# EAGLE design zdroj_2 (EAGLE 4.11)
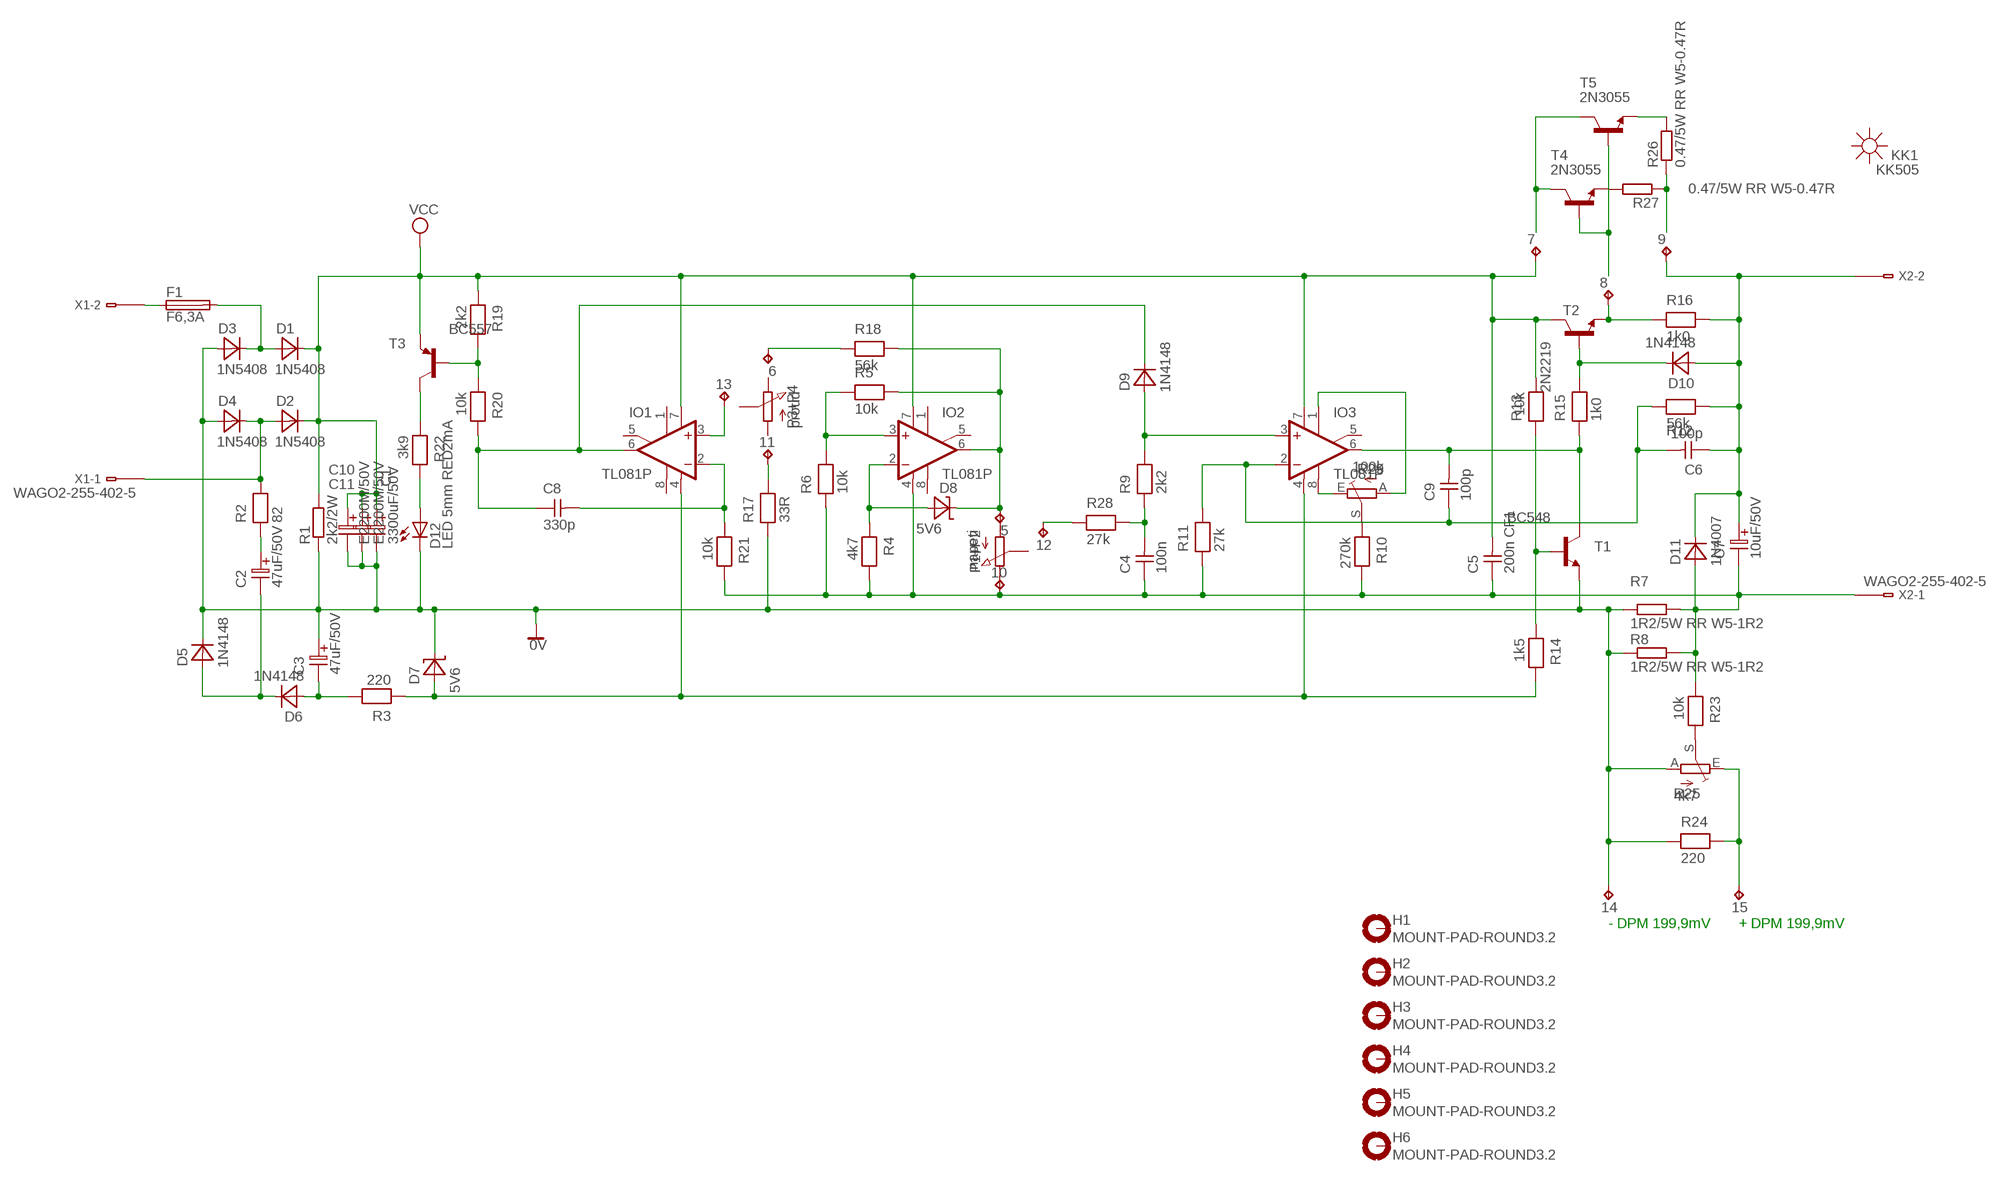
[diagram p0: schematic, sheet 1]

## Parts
5  TPPAD1-13Y  [P1-13Y]
6  TPPAD1-13Y  [P1-13Y]
7  TPPAD1-13Y  [P1-13Y]
8  TPPAD1-13Y  [P1-13Y]
9  TPPAD1-13Y  [P1-13Y]
10  TPPAD1-13Y  [P1-13Y]
11  TPPAD1-13Y  [P1-13Y]
12  TPPAD1-13Y  [P1-13Y]
13  TPPAD1-13Y  [P1-13Y]
14  TPPAD1-13Y  [P1-13Y]
15  TPPAD1-13Y  [P1-13Y]
C1  3300uF/50V  ELC-45L  [E-45L]
C2  47uF/50V  ELC-5  [ES-5]
C3  47uF/50V  ELC-5  [ES-5]
C4  100n  CAPNP-5  [C-5]
C5  200n CF1  CAPNP-5  [C-5]
C6  100p  CAPNP-5  [C-5]
C7  10uF/50V  ELC-2,5L  [ES-2,5L]
C8  330p  CAPNP-5  [C-5]
C9  100p  CAPNP-5  [C-5]
C10  E2200M/50V  ELC-7,5  [ES-7,5]
C11  E2200M/50V  ELC-7,5  [ES-7,5]
D1  1N5408  DIODE-12,5  [D-12,5]
D2  1N5408  DIODE-12,5  [D-12,5]
D3  1N5408  DIODE-12,5  [D-12,5]
D4  1N5408  DIODE-12,5  [D-12,5]
D5  1N4148  DIODE-7,5  [D-7,5]
D6  1N4148  DIODE-7,5  [D-7,5]
D7  5V6  ZDIO-7,5  [D-7,5]
D8  5V6  ZDIO-7,5  [D-7,5]
D9  1N4148  DIODE-7,5  [D-7,5]
D10  1N4148  DIODE-7,5  [D-7,5]
D11  1N4007  DIODE-7,5  [D-7,5]
D12  LED 5mm RED2mA  LED3MM  [LED3MM]
F1  F6,3A  SH22,5A  [SH22,5A]
H1  MOUNT-PAD-ROUND3.2  [3,2-PAD]
H2  MOUNT-PAD-ROUND3.2  [3,2-PAD]
H3  MOUNT-PAD-ROUND3.2  [3,2-PAD]
H4  MOUNT-PAD-ROUND3.2  [3,2-PAD]
H5  MOUNT-PAD-ROUND3.2  [3,2-PAD]
H6  MOUNT-PAD-ROUND3.2  [3,2-PAD]
IO1  TL081P  [DIL08]
IO2  TL081P  [DIL08]
IO3  TL081P  [DIL08]
KK1  KK505  [KK505]
P1+P2  napeti  PC25  [PC25]
P3+P4  proud  PC25  [PC25]
R1  2k2/2W  R-EU_0414/15  [0414/15]
R2  82  RESEU-7,5  [R-7,5]
R3  220  RESEU-7,5  [R-7,5]
R4  4k7  RESEU-7,5  [R-7,5]
R5  10k  RESEU-7,5  [R-7,5]
R6  10k  RESEU-7,5  [R-7,5]
R7  1R2/5W RR W5-1R2  R-EU_0922/22  [0922/22]
R8  1R2/5W RR W5-1R2  R-EU_0922/22  [0922/22]
R9  2k2  RESEU-7,5  [R-7,5]
R10  270k  RESEU-7,5  [R-7,5]
R11  27k  RESEU-7,5  [R-7,5]
R12  56k  RESEU-7,5  [R-7,5]
R13  10k  RESEU-7,5  [R-7,5]
R14  1k5  RESEU-7,5  [R-7,5]
R15  1k0  RESEU-7,5  [R-7,5]
R16  1k0  RESEU-7,5  [R-7,5]
R17  33R  RESEU-7,5  [R-7,5]
R18  56k  RESEU-7,5  [R-7,5]
R19  2k2  RESEU-7,5  [R-7,5]
R20  10k  RESEU-7,5  [R-7,5]
R21  10k  RESEU-7,5  [R-7,5]
R22  3k9  RESEU-7,5  [R-7,5]
R23  10k  RESEU-7,5  [R-7,5]
R24  220  RESEU-7,5  [R-7,5]
R25  4k7  TRIM_EU-CA6V  [CA6V]
R26  0.47/5W RR W5-0.47R  R-EU_0922/22  [0922/22]
R27  0.47/5W RR W5-0.47R  R-EU_0922/22  [0922/22]
R28  27k  RESEU-7,5  [R-7,5]
R29  100k  TRIM_EU-CA6V  [CA6V]
T1  BC548  [TO92-EBC]
T2  2N2219  [TO5]
T3  BC557  [TO92-EBC]
T4  2N3055  2N2219  [TO5]
T5  2N3055  2N2219  [TO5]
X1  WAGO2-255-402-5  [255-402-5]
X2  WAGO2-255-402-5  [255-402-5]

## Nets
0V: 14.1(TP) C1.2 C3.1 C10.2 C11.2 D3.1(A) D4.1(A) D5.2(K) D7.2(K) D12.K(C) R1.1 R7.1 R8.1 R17.1 R24.1 R25.A T1.E
N$1: D2.1(A) D4.2(K) R2.2 X1.B1(-1:B1)
N$2: D1.1(A) D3.2(K) F1.2
N$4: R23.2 R25.S
N$5: F1.1 X1.B2(-2:B1)
N$6: C3.2 D6.1(A) R3.2
N$7: D7.1(A) IO1.4(V-) IO3.4(V-) R3.1 R14.2
N$8: C2.2 D5.1(A) D6.2(K)
N$9: D12.A R22.2
N$10: C2.1 R2.1
N$12: R22.1 T3.C
N$13: R19.2 R20.1 T3.B
N$14: C8.1 D9.2(K) IO1.6(OUT) R20.2
N$15: C8.2 IO1.2(-IN) R21.1
N$16: 8.1(TP) R16.1 T2.1(E)
N$17: 13.1(TP) IO1.3(+IN)
N$18: 6.1(TP) R18.1
N$19: 5.1(TP) D8.2(K) IO2.6(OUT) R5.2 R18.2
N$20: 11.1(TP) R17.2
N$21: D8.1(A) IO2.2(-IN) R4.1
N$22: IO2.3(+IN) R5.1 R6.2
N$23: 12.1(TP) R28.1
N$24: C4.2 R9.1 R28.2
N$25: D9.1(A) IO3.3(+IN) R9.2
N$26: C6.2 C9.1 IO3.2(-IN) R11.2 R12.1
N$27: IO3.1(ON1) R29.A
N$28: IO3.8(OPT) R29.E
N$29: R10.1 R29.S
N$30: C9.2 IO3.6(OUT) R15.1 T1.C
N$31: R13.2 R14.1 T1.B
N$32: D10.2(K) R15.2 T2.2(B)
N$33: 15.1(TP) R24.2 R25.E
N$34: T4.3(C) T5.3(C)
N$35: 9.1(TP) C6.1 C7.1 D10.1(A) D11.2(K) R12.2 R16.2 X2.B2(-2:B1)
N$43: 10.1(TP) C4.1 C5.1 C7.2 D11.1(A) IO2.4(V-) R4.2 R6.1 R7.2 R8.2 R10.2 R11.1 R21.2 R23.1 X2.B1(-1:B1)
N$44: R27.2 T4.1(E)
N$45: R26.2 T5.1(E)
N$46: R26.1 R27.1
N$47: T4.2(B) T5.2(B)
VCC: 7.1(TP) C1.1 C5.2 C10.1 C11.1 D1.2(K) D2.2(K) IO1.7(V+) IO2.7(V+) IO3.7(V+) R1.2 R13.1 R19.1 T2.3(C) T3.E
Unconnected: H1.B3,2(MOUNT) H2.B3,2(MOUNT) H3.B3,2(MOUNT) H4.B3,2(MOUNT) H5.B3,2(MOUNT) H6.B3,2(MOUNT) IO1.1(ON1) IO1.5(ON2) IO1.8(OPT) IO2.1(ON1) IO2.5(ON2) IO2.8(OPT) IO3.5(ON2) P1+P2.A P1+P2.E P1+P2.S P3+P4.A P3+P4.E P3+P4.S X1.A1(-1:A1) X1.A2(-2:A1) X2.A1(-1:A1) X2.A2(-2:A1)

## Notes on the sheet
- - DPM 199,9mV | + DPM 199,9mV

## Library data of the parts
5-15 = testpad:TP
C1 = discrete:ELC-45L
C2 C3 = discrete:ELC-5
C4-C6 C8 C9 = discrete:CAPNP-5
C7 = discrete:ELC-2,5L
C10 C11 = discrete:ELC-7,5
D1-D4 = discrete:DIODE-12,5
D5 D6 D9-D11 = discrete:DIODE-7,5
D7 D8 = discrete:ZDIO-7,5
D12 = led:LED: LED
F1 = fuse:SH22,5A: FUSE HOLDER
H1-H6 = holes:MOUNT-PAD-ROUND: MOUNTING PAD, round
IO1-IO3 = linear:TL081: OP AMP
KK1 = heatsink:KK505: HEATSINK
P1+P2 P3+P4 = pot-vitrohm:PC25: VITROHM POTENTIOMETER
R1 R7 R8 R26 R27 = rcl:R-EU_: RESISTOR, European symbol
R2-R6 R9-R24 R28 = discrete:RESEU-7,5
R25 R29 = pot:TRIM_EU-: POTENTIOMETER
T1 = transistor-npn:BC548*: NPN Transistor
T2 T4 T5 = transistor-npn:2N2219: NPN Transistor
T3 = transistor-pnp:BC557*: PNP Transistror
X1 X2 = con-wago:WAGO2-: WAGO Cage Clamp

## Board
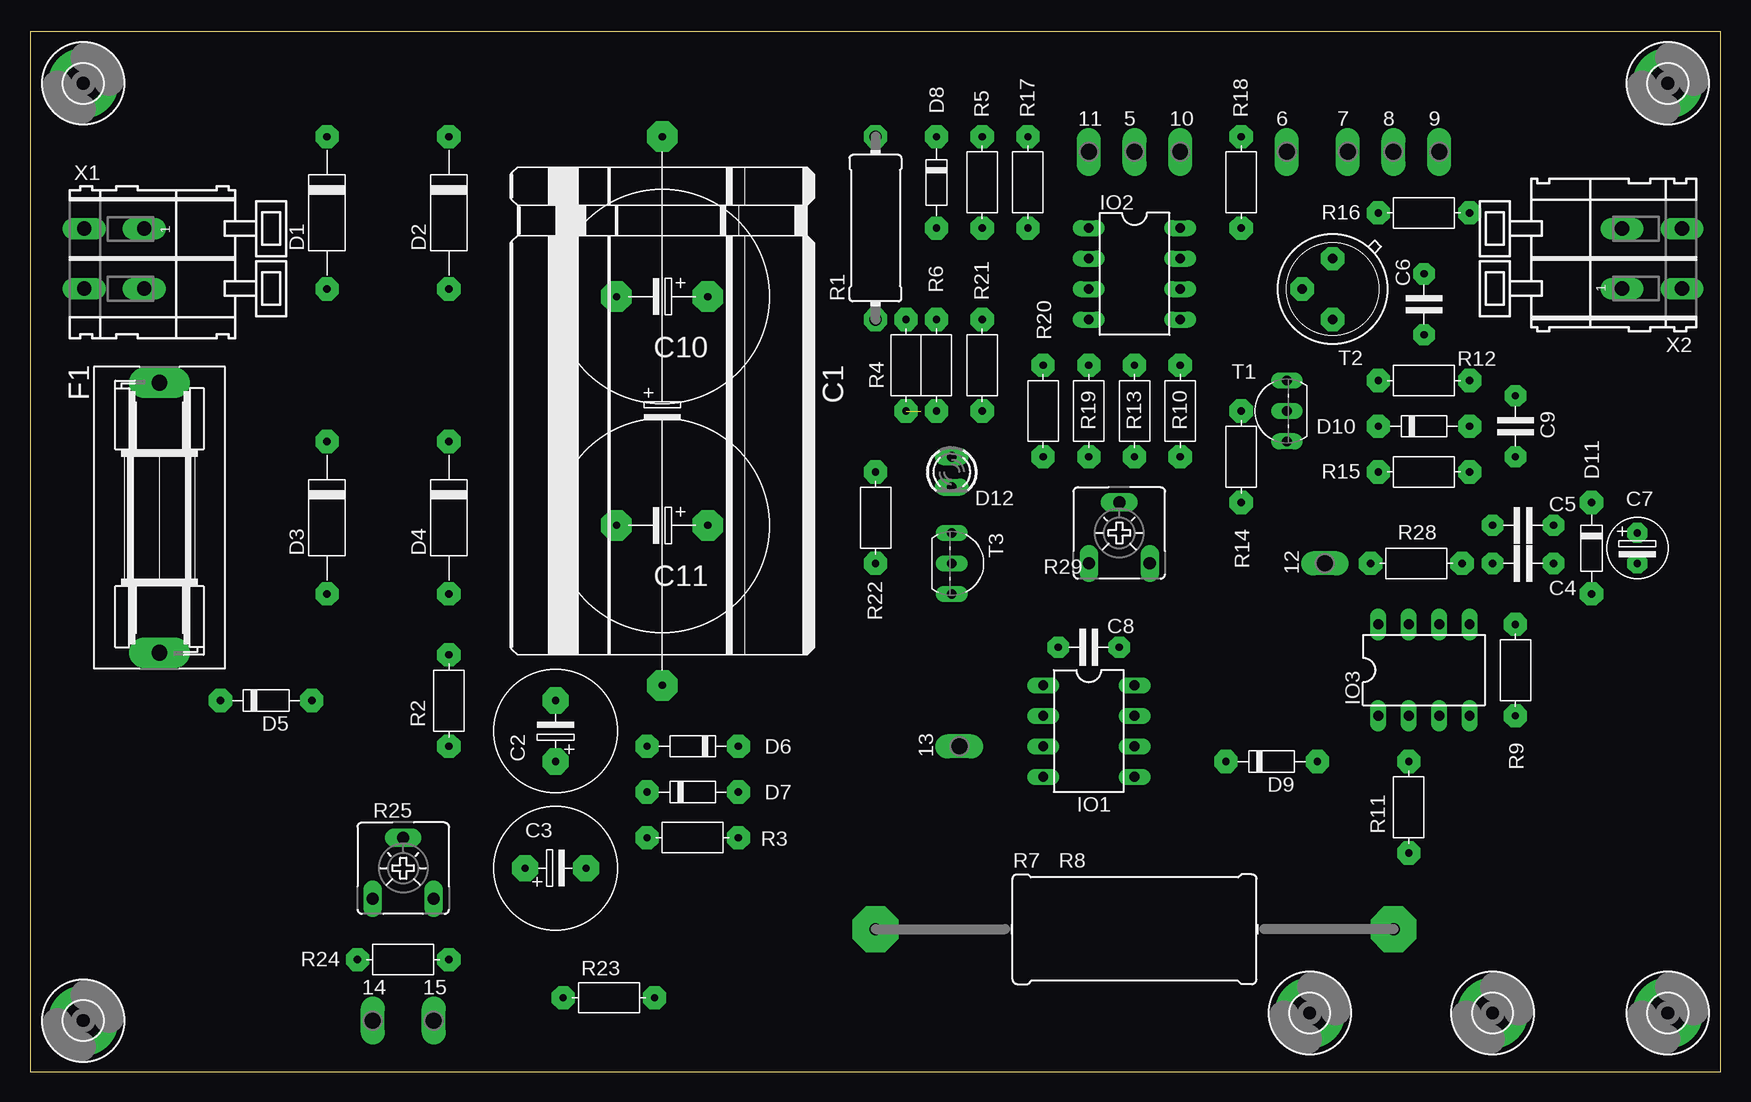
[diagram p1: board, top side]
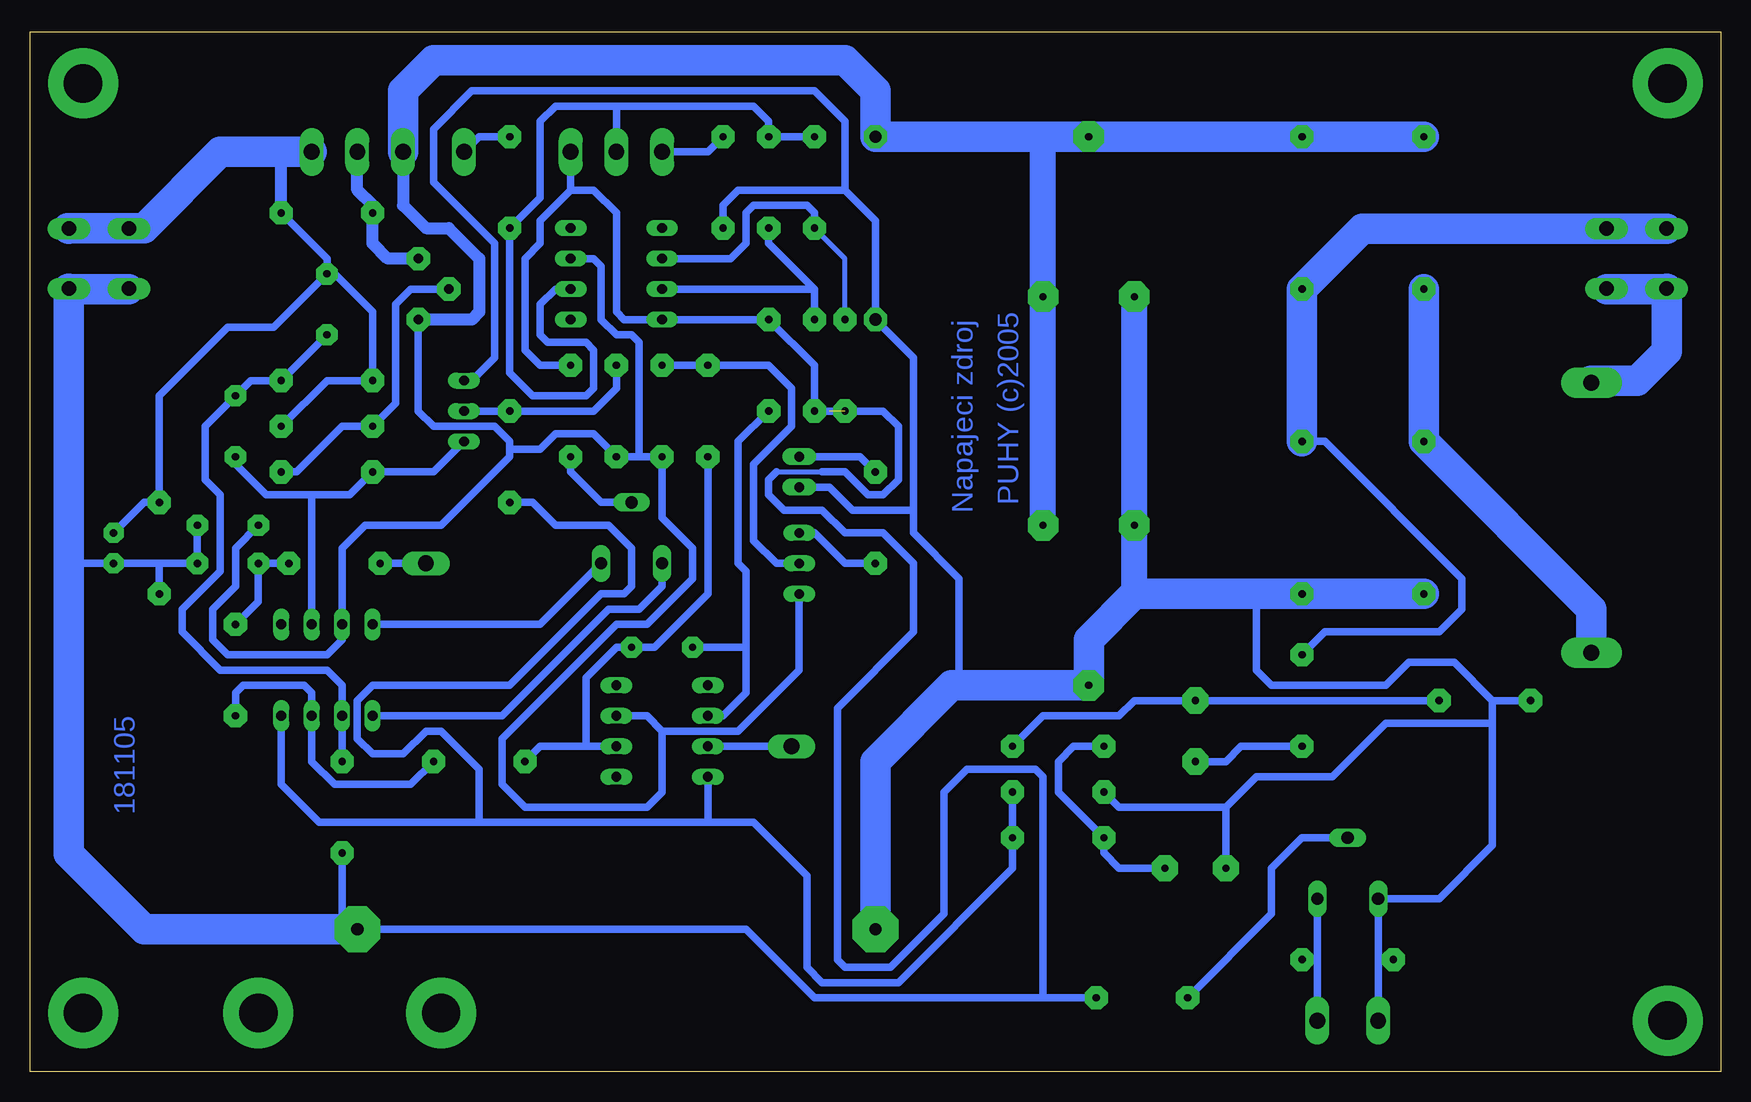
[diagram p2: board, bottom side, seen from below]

Size 140.95 x 86.67 mm. Coordinates in mm from the lower left corner, seen from the top.
Outline: 0,0 140.95,0 140.95,86.67 0,86.67 0,0
Copper layers (1*16): Top 0.035mm / dielectric 1.5mm / Bottom 0.035mm
Design rules "default": minimum track width 10mil, minimum drill 24mil, track to track 8mil, track to pad 8mil, pad to pad 8mil, via to via 8mil, smd to smd 8mil, copper to edge 40mil, drill to drill 8mil, minimum pad ring 10mil, minimum via ring 8mil, stop-mask expansion 4mil, vias tented up to drill 0mil, thermal gap 10mil

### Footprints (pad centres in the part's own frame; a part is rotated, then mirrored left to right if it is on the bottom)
P1-13Y = drill 1.321 pad 1.905 long: 1 0,0
E-45L = drill 0.61 pad 2.54 octagon: 1 0,0; 2 45.72,0
ES-5 = drill 0.61 pad 2.184 octagon: 1 -2.54,0; 2 2.54,0
C-5 = drill 0.61 pad 1.778 octagon: 1 -2.54,0; 2 2.54,0
ES-2,5L = drill 0.61 pad 1.676 octagon: 1 0,0; 2 2.54,0
ES-7,5 = drill 0.61 pad 2.54 octagon: 1 -3.81,0; 2 3.81,0
D-12,5 = drill 0.61 pad 1.93 octagon: 1 -6.35,0; 2 6.35,0
D-7,5 = drill 0.61 pad 1.93 octagon: 1 -3.81,0; 2 3.81,0
LED3MM = drill 0.813 pad 1.422 long: A -1.27,0; K 1.27,0
SH22,5A = drill 1.321 pad 2.54 long: 1 -11.252,0; 2 11.252,0
3,2-PAD = drill 3.2 pad 5.842 round: B3,2 0,0
DIL08 = drill 0.813 long: 1 -3.81,-3.81; 2 -1.27,-3.81; 3 1.27,-3.81; 4 3.81,-3.81; 5 3.81,3.81; 6 1.27,3.81; 7 -1.27,3.81; 8 -3.81,3.81
PC25 = smd 2.2 x 0.8: 4 0,1.65 | smd 0.9 x 1.4: A -1.35,-1.9; E 1.35,-1.9; S 0,-1.9
0414/15 = drill 1.016 pad 1.93 octagon: 1 -7.62,0; 2 7.62,0
R-7,5 = drill 0.61 pad 1.93 octagon: 1 -3.81,0; 2 3.81,0
0922/22 = drill 1.016 pad 3.81 octagon: 1 -21.59,0; 2 21.59,0
CA6V = drill 1.016 long: A -2.54,-2.54; E 2.54,-2.54; S 0,2.54
TO92-EBC = drill 0.813 long: B 0,-1.27; C -2.54,-1.27; E 2.54,-1.27
TO5 = drill 0.813 pad 1.93 octagon: 1 0,-2.54; 2 2.54,0; 3 0,2.54
255-402-5 = drill 1.2 long: A1 -2.5,0; A2 2.5,0; B1 -2.5,-5; B2 2.5,-5

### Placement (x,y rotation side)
5  92.07,76.67 0 top
6  104.77,76.67 0 top
7  109.85,76.67 0 top
8  113.66,76.67 0 top
9  117.47,76.67 0 top
10  95.88,76.67 0 top
11  88.26,76.67 0 top
12  107.94,42.38 90 top
13  77.47,27.14 90 top
14  28.57,4.28 0 top
15  33.65,4.28 0 top
C1  52.7,77.94 270 top
C2  43.81,28.41 90 top
C3  43.81,16.98 0 top
C4  124.46,42.38 180 top
C5  124.46,45.56 180 top
C6  116.2,63.97 270 top
C7  133.98,44.92 270 top
C8  88.26,35.39 180 top
C9  123.82,53.81 270 top
C10  52.7,64.61 180 top
C11  52.7,45.56 180 top
D1  24.76,71.59 90 top
D2  34.92,71.59 90 top
D3  24.76,46.19 90 top
D4  34.92,46.19 90 top
D5  19.68,30.95 180 top
D6  55.24,27.14 0 top
D7  55.24,23.33 180 top
D8  75.56,74.13 90 top
D9  103.5,25.87 180 top
D10  116.2,53.81 180 top
D11  130.17,43.65 90 top
D12  76.83,50 270 top
F1  10.79,46.19 270 top
H1  4.44,82.39 0 top
H2  4.44,4.28 0 top
H3  121.91,4.91 0 top
H4  136.52,4.91 0 top
H5  106.68,4.91 0 top
H6  136.52,82.39 0 top
IO1  88.26,28.41 270 top
IO2  92.07,66.51 270 top
IO3  116.2,33.49 0 top
KK1  not placed on the board
P1+P2  not placed on the board
P3+P4  not placed on the board
R1  70.48,70.32 90 top
R2  34.92,30.95 90 top
R3  55.24,19.52 180 top
R4  73.02,58.89 270 top
R5  79.37,74.13 90 top
R6  75.56,58.89 90 top
R7  92.07,11.9 0 top
R8  92.07,11.9 0 top
R9  123.82,33.49 270 top
R10  95.88,55.08 90 top
R11  114.93,22.06 90 top
R12  116.2,57.62 180 top
R13  92.07,55.08 90 top
R14  100.96,51.27 270 top
R15  116.2,50 0 top
R16  116.2,71.59 0 top
R17  83.18,74.13 90 top
R18  100.96,74.13 270 top
R19  88.26,55.08 90 top
R20  84.45,55.08 270 top
R21  79.37,58.89 90 top
R22  70.48,46.19 90 top
R23  48.25,6.18 180 top
R24  31.11,9.36 0 top
R25  31.11,16.98 0 top
R26  not placed on the board
R27  not placed on the board
R28  115.56,42.38 0 top
R29  90.8,44.92 0 top
T1  103.5,55.08 90 top
T2  108.58,65.24 180 top
T3  78.1,42.38 270 top
T4  not placed on the board
T5  not placed on the board
X1  9.52,67.78 270 top
X2  132.71,67.78 90 top

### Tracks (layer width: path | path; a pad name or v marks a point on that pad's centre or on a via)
0V
  Bottom 0.61: 41.27,22.06 38.73,24.6 32.38,24.6 27.94,29.04 19.04,29.04 | 41.27,22.06 50.16,22.06 D7.2 | 19.04,29.04 19.04,18.89 23.49,14.44 R25.A 28.57,9.36 | 73.02,73.5 81.91,73.5 83.18,72.23 R17.1 | 67.31,46.83 67.31,44.92 63.49,41.11 63.49,32.22 | 67.31,46.83 67.31,59.53 R1.1 70.48,70.95 73.02,73.5 | T1.E 104.13,57.62 102.23,59.53 102.23,69.05 107.31,74.13 107.31,78.58 104.13,81.75 75.56,81.75 73.02,79.21 73.02,73.5 | 67.31,46.83 72.38,46.83 74.29,48.73 D12.K | 38.73,39.84 38.73,33.49 37.46,32.22 27.94,32.22 26.03,34.12 22.22,34.12 19.04,30.95 | 41.27,22.06 C3.1 | 19.04,29.04 19.04,30.95 | 19.04,30.95 D5.2 | 14.1 28.57,9.36 | 28.57,9.36 R24.1
  Bottom 2.184: C10.2 C11.2 48.89,39.84
  Bottom 2.54: R8.1 70.48,25.87 64.13,32.22 63.49,32.22 62.23,32.22 | D3.1 D4.1 38.73,39.84 48.89,39.84 52.7,36.03 C1.2 | C1.2 52.7,33.49 | C1.2 62.23,32.22 | 62.23,32.22 62.86,32.22
N$1
  Bottom 0.61: R2.2 33.02,36.67 23.49,36.67 21.59,38.57 21.59,41.11 33.02,52.54 D4.2
  Bottom 2.54: X1.B1 29.88,70.28 D2.1 D4.2
N$2
  Bottom 2.54: D1.1 D3.2 10.79,38.57 F1.2
N$3
  Bottom 2.54: 132.71,65.24 137.79,65.24
N$4
  Bottom 0.61: R25.S 34.92,19.52 37.46,16.98 37.46,13.17 R23.2
N$5
  Bottom 2.54: X1.B2 4.52,60.08 6.98,57.62 10.79,57.62 F1.1
N$6
  Bottom 0.61: D6.1 53.97,27.14 55.24,25.87 55.24,23.33 R3.2 51.43,18.25 50.16,16.98 C3.2
N$7
  Bottom 0.61: IO3.4 120.01,23.96 116.84,20.79 103.5,20.79 | 84.45,20.79 80.64,20.79 76.19,16.34 76.19,8.73 74.92,7.46 68.58,7.46 59.05,16.98 R3.1 D7.1 | 84.45,20.79 103.5,20.79 | 84.45,20.79 IO1.4 | 103.5,20.79 103.5,25.24 106.68,28.41 107.94,28.41 109.85,26.5 112.39,26.5 113.66,27.78 113.66,30.95 112.39,32.22 100.96,32.22 93.34,39.84 91.44,39.84 90.8,40.47 90.8,43.65 92.71,45.56 97.15,45.56 99.06,47.46 R14.2
N$8
  Bottom 0.61: D5.1 C2.2 48.89,30.95 50.16,29.68 56.51,29.68 D6.2
N$9
  Bottom 0.61: R22.2 71.75,51.27 D12.A
N$10
  Bottom 0.61: R2.1 40,27.14 41.27,25.87 C2.1
N$12
  Bottom 0.61: R22.1 73.02,42.38 75.56,44.92 T3.C
N$13
  Bottom 0.61: T3.B 78.73,42.38 80.64,44.28 80.64,50.64 77.47,53.81 77.47,56.98 79.37,58.89 R20.1 R19.2
N$14
  Bottom 0.61: D9.2 98.42,27.14 94.61,27.14 | IO1.6 94.61,27.14 | 94.61,27.14 94.61,32.86 92.07,35.39 C8.1 88.9,35.39 84.45,39.84 R20.2
N$15
  Bottom 0.61: IO1.2 83.18,29.68 81.28,31.58 81.28,35.39 | 81.28,35.39 C8.2 | R21.1 81.91,52.54 81.91,42.38 81.28,41.75 81.28,35.39
N$16
  Bottom 1.016: T2.1 111.12,67.78 112.39,69.05 R16.1 112.39,72.23 113.66,73.5 8.1
N$17
  Bottom 0.61: 13.1 IO1.3
N$18
  Bottom 0.61: R18.1 103.5,77.94 6.1
N$19
  Bottom 0.61: D8.2 R5.2 79.37,79.21 80.64,80.48 92.07,80.48 | 92.07,80.48 97.15,80.48 98.42,79.21 98.42,72.86 R18.2 100.96,58.26 99.06,56.35 94.61,56.35 93.97,56.98 93.97,60.16 94.61,60.8 97.78,60.8 98.42,61.43 98.42,63.97 97.15,65.24 IO2.6 | 92.07,80.48 5.1
N$20
  Bottom 0.61: 11.1 84.45,76.67 R17.2
N$21
  Bottom 0.406: R4.1 73.02,67.78 D8.1
  Bottom 0.61: D8.1 75.56,71.59 76.19,72.23 80.64,72.23 81.28,71.59 81.28,69.05 82.55,67.78 IO2.2
N$22
  Bottom 0.61: R6.2 75.56,65.24 | 75.56,65.24 IO2.3 | 75.56,65.24 79.37,69.05 R5.1
N$23
  Bottom 0.61: 12.1 R28.1
N$24
  Bottom 0.61: R9.1 121.91,39.2 C4.2 R28.2
N$25
  Bottom 0.61: D9.1 109.22,23.96 115.56,23.96 117.47,25.87 IO3.3 117.47,31.58 118.1,32.22 123.19,32.22 123.82,31.58 R9.2
N$26
  Bottom 0.61: C6.2 R12.1 122.55,57.62 C9.1 126.36,53.81 126.36,49.37 125.09,48.09 125.09,41.75 128.26,38.57 128.26,36.67 125.09,33.49 116.2,33.49 114.93,32.22 IO3.2 R11.2
N$27
  Bottom 0.61: 111.75,29.68 IO3.1 101.59,29.68 92.71,38.57 90.16,38.57 88.26,40.47 R29.A
N$28
  Bottom 0.61: R29.E 98.42,37.3 IO3.8
N$29
  Bottom 0.61: R29.S 93.34,47.46 95.88,50 R10.1
N$30
  Bottom 0.61: T1.C 107.31,50 R15.1 114.29,48.09 117.47,48.09 | 117.47,48.09 121.28,48.09 123.82,50.64 C9.2 | IO3.6 117.47,48.09
N$31
  Bottom 0.61: R13.2 92.07,56.98 93.97,55.08 T1.B R14.1
N$32
  Bottom 0.61: T2.2 109.22,65.24 110.49,63.97 110.49,55.72 D10.2 114.93,53.81 118.74,50 R15.2
N$33
  Bottom 0.61: 15.1 33.65,9.36 | 33.65,9.36 R25.E | 33.65,9.36 R24.2
N$34  (1 unrouted)
N$35
  Bottom 0.61: R16.2 116.2,67.78 C6.1 | C6.1 120.65,62.06 124.46,62.06 130.17,56.35 D11.2 131.44,47.46 C7.1 | D10.1 116.2,57.62 R12.2 112.39,63.34 115.56,66.51 C6.1
  Bottom 1.016: R16.2 120.01,76.67
  Bottom 2.54: 9.1 120.01,76.67 125.09,76.67 131.44,70.32 137.75,70.32 | 137.75,70.32 137.79,70.32 | 137.75,70.32 X2.B2
N$42
  Bottom 2.54: 4.44,65.24 9.52,65.24
N$43  (1 unrouted)
  Bottom 0.406: 78.73,50 74.92,50 | 74.29,55.08 R6.1
  Bottom 0.61: 74.92,55.08 74.29,55.08 69.84,55.08 68.58,53.81 68.58,49.37 69.84,48.09 71.12,48.09 73.02,50 74.92,50 | 78.73,50 79.37,49.37 79.37,48.09 78.1,46.83 74.92,46.83 73.02,44.92 69.84,44.92 67.31,42.38 67.31,36.67 73.66,30.32 73.66,9.36 73.02,8.73 69.21,8.73 64.77,13.17 64.77,23.33 62.86,25.24 57.15,25.24 56.51,24.6 56.51,6.18 | R6.1 75.56,58.89 R21.2 IO2.4 91.44,62.7 92.07,63.34 92.07,71.59 93.97,73.5 95.88,73.5 | 95.88,75.4 10.1 95.88,73.5 | 137.79,32.22 137.71,42.38 C7.2 130.17,42.38 | R10.2 98.42,58.89 99.69,60.16 99.69,67.78 98.42,69.05 98.42,70.95 95.88,73.5 | 114.93,11.9 R11.1 | 130.17,42.38 D11.1 | 130.17,42.38 C4.1 C5.1 | R8.2 81.28,11.9 75.56,6.18 56.51,6.18 | R23.1 56.51,6.18
  Bottom 2.54: X2.B1 137.71,42.38 137.71,18.17 131.44,11.9 114.93,11.9 R8.2
N$44  (1 unrouted)
N$45  (1 unrouted)
N$46  (1 unrouted)
N$47  (1 unrouted)
VCC
  Bottom 0.61: D1.2 25.39,77.94 | IO2.7 93.97,67.78 93.34,67.15 93.34,62.7 92.07,61.43 90.8,61.43 90.16,60.8 90.16,51.27 | 90.16,51.27 R19.1 88.26,46.19 85.72,43.65 85.72,41.11 89.53,37.3 92.07,37.3 101.59,27.78 101.59,23.96 99.69,22.06 89.53,22.06 88.26,23.33 88.26,28.41 | 90.16,51.27 R13.1 93.97,53.17 97.15,53.17 98.42,51.91 100.96,51.91 | IO1.7 89.53,29.68 88.26,28.41 | 88.26,28.41 81.91,28.41 76.83,33.49 T3.E | T2.3 108.58,55.08 107.31,53.81 102.23,53.81 100.96,52.54 100.96,51.91 | 100.96,51.91 100.96,51.27 106.68,45.56 113.03,45.56 114.93,43.65 IO3.7 114.93,36.03 116.2,34.76 124.46,34.76 125.72,36.03 125.72,38.57 123.82,40.47 123.82,43.65 C5.2
  Bottom 1.016: 7.1 109.85,72.23 107.94,70.32 106.04,70.32 103.5,67.78 103.5,63.34 104.13,62.7 T2.3
  Bottom 2.184: 56.51,77.94 C10.1 C11.1
  Bottom 2.54: 7.1 109.85,81.75 107.31,84.29 73.02,84.29 70.48,81.75 R1.2 56.51,77.94 C1.1 D2.2 D1.2

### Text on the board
Bottom: PUHY (c)2005 | Napajeci zdroj | 181105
